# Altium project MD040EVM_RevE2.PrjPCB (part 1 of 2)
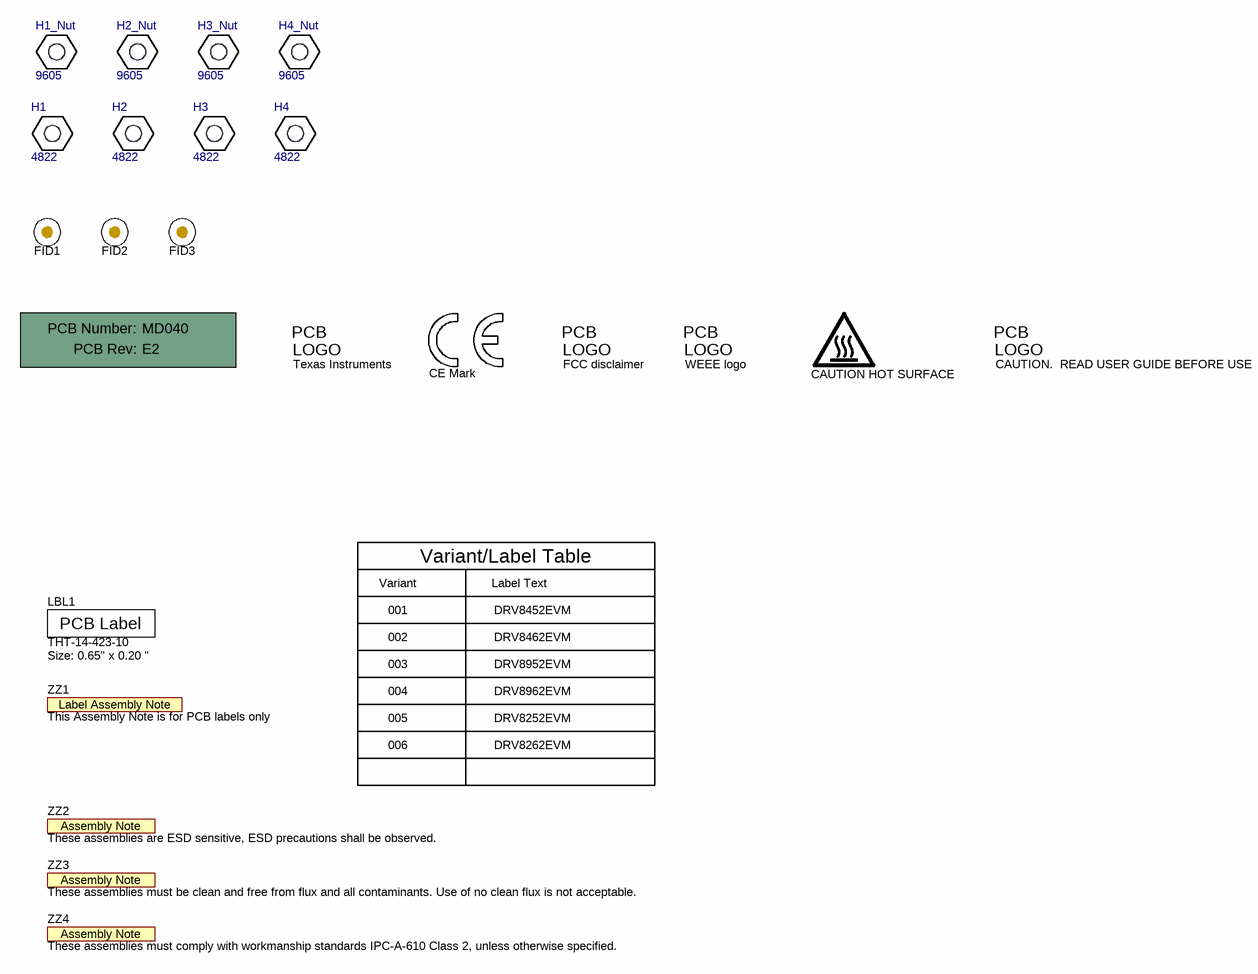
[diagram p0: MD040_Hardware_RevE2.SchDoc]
CopyrightYear: 2021; PCB_Layout: Wang Li; PCB_Rev: E2; PRJ_Customer: Public Release; PRJ_Engineer: Wang Li; PRJ_Number: MD040; PRJ_Title: DRV8452EVM; SCH_Rev: E2; TechSupport: http://www.ti.com/support; TID: N/A
4 sheets, 334 parts. Net scope: global (net labels, ports and power ports of the same name join across sheets).
Board file: MD040_RevE2.PcbDoc
Sheets:
  MD040_Hardware_RevE2.SchDoc
  MD040_Motor_control_RevE2.SchDoc
  MD040_Motor_Driver_RevE2.SchDoc
  MD040_ezFET_RevE2.SchDoc

## Sheet MD040_Hardware_RevE2.SchDoc
size 431 x 279 mm; Date: Not shown in title block; ApprovedBy: Not shown in title block; CheckedBy: Not shown in title block; Author: Not shown in title block; CompanyName: Not shown in title block; Engineer: Not shown in title block; Organization: Not shown in title block; Address1: Not shown in title block; Address2: Not shown in title block; Address3: Not shown in title block; Address4: Not shown in title block; DocumentNumber: 3; Revision: Use project parameter SCH_Rev; SheetNumber: 3; SheetTotal: 3; PageSetup: Record=PageOptions¦CenterHorizontal=True¦CenterVertical=True¦PrintScale=1.00¦XCorrection=1.00¦YCorrection=1.00¦PrintKind=0¦BorderSize=5000000¦LeftOffset=0¦BottomOffset=0¦Orientation=2¦PaperLength=1000¦PaperWidth=1000¦Scale=100¦PaperSource=15¦PrintQuality=600¦MediaType=1¦DitherType=10¦PaperKind=Letter¦PrintScaleMode=1

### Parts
!PCB1  Printed Circuit Board  (value not drawn)  (mechanical)
FID1  Fiducial  [Fiducial10-20]  (value not drawn)
FID2  Fiducial  [Fiducial10-20]  (value not drawn)
FID3  Fiducial  [Fiducial10-20]  (value not drawn)
H1  4822  [KEYSTONE_4822]
H1_Nut  9605  [Keystone_9605]
H2  4822  [KEYSTONE_4822]
H2_Nut  9605  [Keystone_9605]
H3  4822  [KEYSTONE_4822]
H3_Nut  9605  [Keystone_9605]
H4  4822  [KEYSTONE_4822]
H4_Nut  9605  [Keystone_9605]
LBL1  THT-14-423-10  Note: Size: 0.65" x 0.20 "  [Label_650x200]
LOGO1  CAUTION HOT SURFACE  [IEC_HotSurface_Small]  (no BOM)
Logo2  CE Mark  [CE_Mark_5mm]  (no BOM)
Logo3  Texas Instruments  [TI_Stacked_Overlay_Small]  (no BOM)
Logo4  FCC disclaimer  [FCC_disclaimer]  (no BOM)
Logo5  WEEE logo  [WEEE_Minimum]  (no BOM)
Logo6  CAUTION.  READ USER GUIDE BEFORE USE  [IEC_Caution_Small]  (no BOM)
ZZ1  This Assembly Note is for PCB labels only  [AssemblyNoteLabel]  (no BOM)
ZZ2  These assemblies are ESD sensitive, ESD precautions shall be observed.  [AssemblyNote]  (no BOM)
ZZ3  These assemblies must be clean and free from flux and all contaminants. Use of no clean flux is not acceptable.  [AssemblyNote]  (no BOM)
ZZ4  These assemblies must comply with workmanship standards IPC-A-610 Class 2, unless otherwise specified.  [AssemblyNote]  (no BOM)

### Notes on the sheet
- Variant
- Variant/Label Table
- Label Text
- 001
- 002
- DRV8452EVM
- DRV8462EVM
- 003
- 004
- 005
- DRV8952EVM
- DRV8962EVM
- DRV8252EVM
- 006
- DRV8262EVM

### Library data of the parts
!PCB1 = CMP-0003618-2: Manufacturer: Any; PartNumber: MD040
FID1-FID3 = CMP-0077181-1: Fiducial mark.  There is nothing to buy or mount.
H1-H4 = CMP-0003678-1: Standoff, Hex, 1.25"L #6-32 Nylon; Manufacturer: Keystone
H1_Nut H2_Nut H3_Nut H4_Nut = CMP-0003948-1: Small nylon hex nut, 0.10 thick with a 0.250 outside diameter and a 4-40 threading; Manufacturer: Keystone; CompType: Standoff
LBL1 = CMP-0003625-1: Thermal Transfer Printable Labels, 0.650" W x 0.200" H - 10,000 per roll; Manufacturer: Brady; CompType: Label
LOGO1 = CMP-0074837-1: IEC 61010-1 Hot Surface Warning; SymbolCreator: a0412235
Logo2 = CMP-0074844-1: SymbolCreator: a0412235
Logo3 = CMP-0074838-1: Texas Instrument Corporate Signature; SymbolCreator: a0412235; Lib Reference: TI_Logo; Library Reference: Logo
Logo4 = CMP-0074847-1: FCC_disclaimer; Library Reference: Logo
Logo5 = CMP-0074769-1
Logo6 = CMP-0074836-1: IEC 61010-1 Caution Warning; SymbolCreator: a0412235; Lib Reference: IEC_Caution
ZZ1 = CMP-0003616-3
ZZ2 = CMP-0077236-1
ZZ3 = CMP-0077237-1
ZZ4 = CMP-0077238-1

## Sheet MD040_Motor_control_RevE2.SchDoc
size 431 x 279 mm; Date: Not shown in title block; ApprovedBy: Not shown in title block; CheckedBy: Not shown in title block; Author: Not shown in title block; CompanyName: Not shown in title block; Engineer: Not shown in title block; Organization: Not shown in title block; Address1: Not shown in title block; Address2: Not shown in title block; Address3: Not shown in title block; Address4: Not shown in title block; DocumentNumber: 2; Revision: Use project parameter SCH_Rev; SheetNumber: 2; SheetTotal: 3; PageSetup: Record=PageOptions¦CenterHorizontal=True¦CenterVertical=True¦PrintScale=1.00¦XCorrection=1.00¦YCorrection=1.00¦PrintKind=0¦BorderSize=5000000¦LeftOffset=0¦BottomOffset=0¦Orientation=2¦PaperLength=1000¦PaperWidth=1000¦Scale=100¦PaperSource=15¦PrintQuality=600¦MediaType=1¦DitherType=10¦PaperKind=Letter¦PrintScaleMode=1
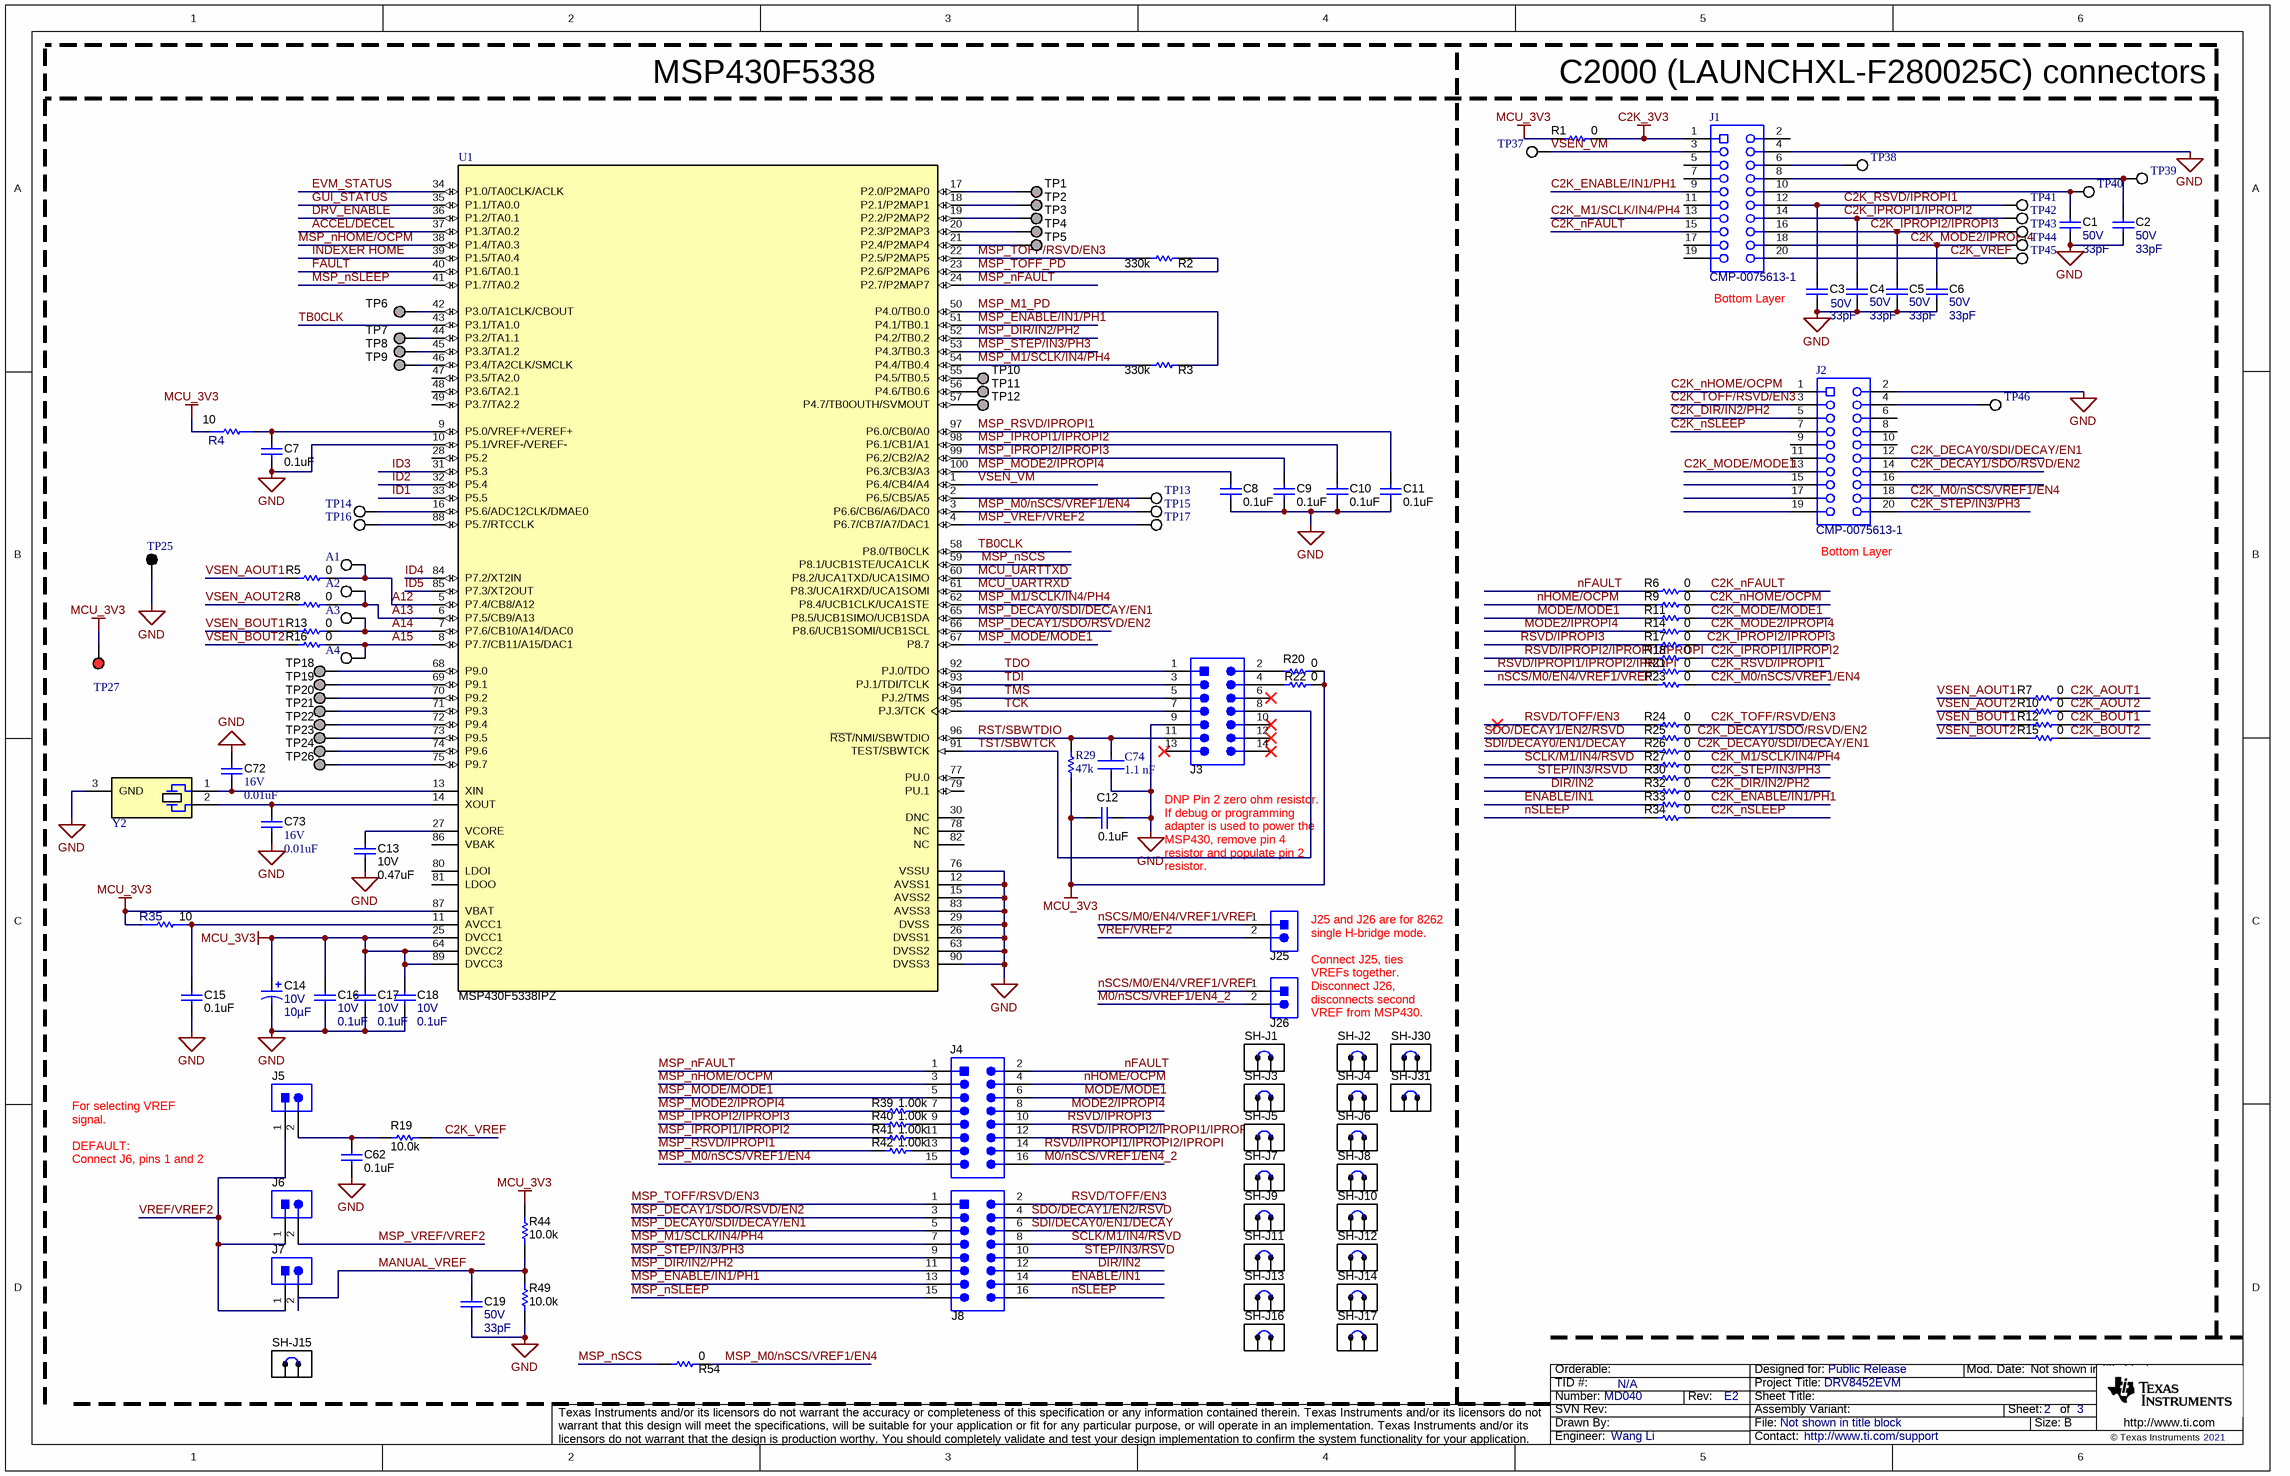
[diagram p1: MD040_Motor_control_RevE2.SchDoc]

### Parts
A1  5012  [Keystone5012]  (value not drawn)
A2  5012  [Keystone5012]  (value not drawn)
A3  5012  [Keystone5012]  (value not drawn)
A4  5012  [Keystone5012]  (value not drawn)
C1  VDC_V: 50V  ValueDisplayed: 33pF  [0402]  (hidden comment: C1005C0G1H330J050BA)
C2  VDC_V: 50V  ValueDisplayed: 33pF  [0402]  (hidden comment: C1005C0G1H330J050BA)
C3  VDC_V: 50V  ValueDisplayed: 33pF  [0402]  (hidden comment: C1005C0G1H330J050BA)
C4  VDC_V: 50V  ValueDisplayed: 33pF  [0402]  (hidden comment: C1005C0G1H330J050BA)
C5  VDC_V: 50V  ValueDisplayed: 33pF  [0402]  (hidden comment: C1005C0G1H330J050BA)
C6  VDC_V: 50V  ValueDisplayed: 33pF  [0402]  (hidden comment: C1005C0G1H330J050BA)
C7  ValueDisplayed: 0.1uF  [0402L]  (hidden comment: 885012105010)
C8  ValueDisplayed: 0.1uF  [0402L]  (hidden comment: 885012105010)
C9  ValueDisplayed: 0.1uF  [0402L]  (hidden comment: 885012105010)
C10  ValueDisplayed: 0.1uF  [0402L]  (hidden comment: 885012105010)
C11  ValueDisplayed: 0.1uF  [0402L]  (hidden comment: 885012105010)
C12  ValueDisplayed: 0.1uF  [0402L]  (hidden comment: 885012105010)
C13  VDC_V: 10V  ValueDisplayed: 0.47uF  [0402]  (hidden comment: GRM155R61A474KE15D)
C14  VDC_V: 10V  ValueDisplayed: 10µF  [3216-18]  (hidden comment: T520A106M010ATE080)
C15  ValueDisplayed: 0.1uF  [0402L]  (hidden comment: 885012105010)
C16  VDC_V: 10V  ValueDisplayed: 0.1uF  [0402]  (hidden comment: GRM155R61A104KA01D)
C17  VDC_V: 10V  ValueDisplayed: 0.1uF  [0402]  (hidden comment: GRM155R61A104KA01D)
C18  VDC_V: 10V  ValueDisplayed: 0.1uF  [0402]  (hidden comment: GRM155R61A104KA01D)
C19  VDC_V: 50V  ValueDisplayed: 33pF  [0402]  (hidden comment: C1005C0G1H330J050BA)
C62  ValueDisplayed: 0.1uF  [0402L]  (hidden comment: 885012105010)
C72  VDC_V: 16V  ValueDisplayed: 0.01uF  [0402]  (hidden comment: 885012205031)
C73  VDC_V: 16V  ValueDisplayed: 0.01uF  [0402]  (hidden comment: 885012205031)
C74  1.1 nF  [FP-C0805C-DN-MFG]
J1  CMP-0075613-1  [Samtec_SSQ-110-03-x-D]
J2  CMP-0075613-1  [Samtec_SSQ-110-03-x-D]
J3  Header_7x2_PEC07DAAN  [CONN_PEC07DAAN]  (value not drawn)
J4  TSM-108-01-L-DV  [Samtec_TSM-108-01-x-DV]  (value not drawn)
J5  PBC02SAAN  [Sullins_PBC02SAAN]  (value not drawn)
J6  PBC02SAAN  [Sullins_PBC02SAAN]  (value not drawn)
J7  PBC02SAAN  [Sullins_PBC02SAAN]  (value not drawn)
J8  TSM-108-01-L-DV  [Samtec_TSM-108-01-x-DV]  (value not drawn)
J25  PBC02SAAN  [Sullins_PBC02SAAN]  (value not drawn)
J26  PBC02SAAN  [Sullins_PBC02SAAN]  (value not drawn)
R1  value 0  [0402L]  (hidden comment: Resistor)
R2  ValueDisplayed: 330k  [0603L]  (hidden comment: CRCW0603330KJNEA)
R3  ValueDisplayed: 330k  [0603L]  (hidden comment: CRCW0603330KJNEA)
R4  Res_ohm: 10  [FP-CH0402-10RJFPT_0402-MFG]  (hidden comment: CH0402-10RJFPT)
R5  value 0  [0402L]  (hidden comment: Resistor)
R6  value 0  [0402L]  (hidden comment: Resistor)
R7  value 0  [0402L]  (hidden comment: Resistor)
R8  value 0  [0402L]  (hidden comment: Resistor)
R9  value 0  [0402L]  (hidden comment: Resistor)
R10  value 0  [0402L]  (hidden comment: Resistor)
R11  value 0  [0402L]  (hidden comment: Resistor)
R12  value 0  [0402L]  (hidden comment: Resistor)
R13  value 0  [0402L]  (hidden comment: Resistor)
R14  value 0  [0402L]  (hidden comment: Resistor)
R15  value 0  [0402L]  (hidden comment: Resistor)
R16  value 0  [0402L]  (hidden comment: Resistor)
R17  value 0  [0402L]  (hidden comment: Resistor)
R18  value 0  [0402L]  (hidden comment: Resistor)
R19  ValueDisplayed: 10.0k  [0603]  (hidden comment: CRCW060310K0FKEA)
R20  value 0  [0402L]  (hidden comment: Resistor)
R21  value 0  [0402L]  (hidden comment: Resistor)
R22  value 0  [0402L]  (hidden comment: Resistor)
R23  value 0  [0402L]  (hidden comment: Resistor)
R24  value 0  [0402L]  (hidden comment: Resistor)
R25  value 0  [0402L]  (hidden comment: Resistor)
R26  value 0  [0402L]  (hidden comment: Resistor)
R27  value 0  [0402L]  (hidden comment: Resistor)
R29  47k  [RESC1005X40X25ML05T10]
R30  value 0  [0402L]  (hidden comment: Resistor)
R32  value 0  [0402L]  (hidden comment: Resistor)
R33  value 0  [0402L]  (hidden comment: Resistor)
R34  value 0  [0402L]  (hidden comment: Resistor)
R35  Res_ohm: 10  [FP-CH0402-10RJFPT_0402-MFG]  (hidden comment: CH0402-10RJFPT)
R39  ValueDisplayed: 1.00k  [0402L]  (hidden comment: CRCW04021K00FKED)
R40  ValueDisplayed: 1.00k  [0402L]  (hidden comment: CRCW04021K00FKED)
R41  ValueDisplayed: 1.00k  [0402L]  (hidden comment: CRCW04021K00FKED)
R42  ValueDisplayed: 1.00k  [0402L]  (hidden comment: CRCW04021K00FKED)
R44  ValueDisplayed: 10.0k  [0603]  (hidden comment: CRCW060310K0FKEA)
R49  ValueDisplayed: 10.0k  [0603]  (hidden comment: CRCW060310K0FKEA)
R54  value 0  [0402L]  (hidden comment: Resistor)
SH-J1  SNT-100-BK-G  [SNT-100-BK-G]  (value not drawn)
SH-J2  SNT-100-BK-G  [SNT-100-BK-G]  (value not drawn)
SH-J3  SNT-100-BK-G  [SNT-100-BK-G]  (value not drawn)
SH-J4  SNT-100-BK-G  [SNT-100-BK-G]  (value not drawn)
SH-J5  SNT-100-BK-G  [SNT-100-BK-G]  (value not drawn)
SH-J6  SNT-100-BK-G  [SNT-100-BK-G]  (value not drawn)
SH-J7  SNT-100-BK-G  [SNT-100-BK-G]  (value not drawn)
SH-J8  SNT-100-BK-G  [SNT-100-BK-G]  (value not drawn)
SH-J9  SNT-100-BK-G  [SNT-100-BK-G]  (value not drawn)
SH-J10  SNT-100-BK-G  [SNT-100-BK-G]  (value not drawn)
SH-J11  SNT-100-BK-G  [SNT-100-BK-G]  (value not drawn)
SH-J12  SNT-100-BK-G  [SNT-100-BK-G]  (value not drawn)
SH-J13  SNT-100-BK-G  [SNT-100-BK-G]  (value not drawn)
SH-J14  SNT-100-BK-G  [SNT-100-BK-G]  (value not drawn)
SH-J15  SNT-100-BK-G  [SNT-100-BK-G]  (value not drawn)
SH-J16  SNT-100-BK-G  [SNT-100-BK-G]  (value not drawn)
SH-J17  SNT-100-BK-G  [SNT-100-BK-G]  (value not drawn)
SH-J30  SNT-100-BK-G  [SNT-100-BK-G]  (value not drawn)
SH-J31  SNT-100-BK-G  [SNT-100-BK-G]  (value not drawn)
TP1  TP_H0.45P0.75  [TP_H045P075]  (value not drawn)  (no BOM)
TP2  TP_H0.45P0.75  [TP_H045P075]  (value not drawn)  (no BOM)
TP3  TP_H0.45P0.75  [TP_H045P075]  (value not drawn)  (no BOM)
TP4  TP_H0.45P0.75  [TP_H045P075]  (value not drawn)  (no BOM)
TP5  TP_H0.45P0.75  [TP_H045P075]  (value not drawn)  (no BOM)
TP6  TP_H0.45P0.75  [TP_H045P075]  (value not drawn)  (no BOM)
TP7  TP_H0.45P0.75  [TP_H045P075]  (value not drawn)  (no BOM)
TP8  TP_H0.45P0.75  [TP_H045P075]  (value not drawn)  (no BOM)
TP9  TP_H0.45P0.75  [TP_H045P075]  (value not drawn)  (no BOM)
TP10  TP_H0.45P0.75  [TP_H045P075]  (value not drawn)  (no BOM)
TP11  TP_H0.45P0.75  [TP_H045P075]  (value not drawn)  (no BOM)
TP12  TP_H0.45P0.75  [TP_H045P075]  (value not drawn)  (no BOM)
TP13  5012  [Keystone5012]  (value not drawn)
TP14  5012  [Keystone5012]  (value not drawn)
TP15  5012  [Keystone5012]  (value not drawn)
TP16  5012  [Keystone5012]  (value not drawn)
TP17  5012  [Keystone5012]  (value not drawn)
TP18  TP_H0.45P0.75  [TP_H045P075]  (value not drawn)  (no BOM)
TP19  TP_H0.45P0.75  [TP_H045P075]  (value not drawn)  (no BOM)
TP20  TP_H0.45P0.75  [TP_H045P075]  (value not drawn)  (no BOM)
TP21  TP_H0.45P0.75  [TP_H045P075]  (value not drawn)  (no BOM)
TP22  TP_H0.45P0.75  [TP_H045P075]  (value not drawn)  (no BOM)
TP23  TP_H0.45P0.75  [TP_H045P075]  (value not drawn)  (no BOM)
TP24  TP_H0.45P0.75  [TP_H045P075]  (value not drawn)  (no BOM)
TP25  5011  [Keystone5011]  (value not drawn)
TP26  TP_H0.45P0.75  [TP_H045P075]  (value not drawn)  (no BOM)
TP27  5010  [Keystone5010]  (value not drawn)
TP37  5012  [Keystone5012]  (value not drawn)
TP38  5012  [Keystone5012]  (value not drawn)
TP39  5012  [Keystone5012]  (value not drawn)
TP40  5012  [Keystone5012]  (value not drawn)
TP41  5012  [Keystone5012]  (value not drawn)
TP42  5012  [Keystone5012]  (value not drawn)
TP43  5012  [Keystone5012]  (value not drawn)
TP44  5012  [Keystone5012]  (value not drawn)
TP45  5012  [Keystone5012]  (value not drawn)
TP46  5012  [Keystone5012]  (value not drawn)
U1  MSP430F5338IPZ  [PZT0100A_N]
Y2  MS3V-T1R 32.768KHZ +/-20PPM 12.5PF  [XTAL_MS3V-T1R]  (value not drawn)

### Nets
C2K_3V3: J1.1 R1.2
GND: C1.2 C2.2 C3.2 C4.2 C5.2 C6.2 C7.1 C8.1 C9.1 C10.1 C11.1 C12.2 C13.2 C14.2(-) C15.1 C16.2 C17.2 C18.2 C19.2 C62.1 C72.2 C73.1 C74.2 J1.4 J2.2 J3.9 R49.1 TP25.1 U1.10(P5.1/VREF-/VEREF-) U1.12(AVSS1) U1.15(AVSS2) U1.26(DVSS1) U1.29(DVSS) U1.63(DVSS2) U1.76(VSSU) U1.83(AVSS3) U1.90(DVSS3) Y2.3(GND)
MCU_3V3: C12.1 C14.1(+) C16.1 C17.1 C18.1 R1.1 R4.1 R20.2 R22.2 R29.1 R35.1 R44.2 TP27.1 U1.25(DVCC1) U1.64(DVCC2) U1.87(VBAT) U1.89(DVCC3)
A12: A1.1 R5.2 U1.5(P7.4/CB8/A12)
A13: A2.1 R8.2 U1.6(P7.5/CB9/A13)
A14: A3.1 R13.2 U1.7(P7.6/CB10/A14/DAC0)
A15: A4.1 R16.2 U1.8(P7.7/CB11/A15/DAC1)
ACCEL/DECEL: U1.37(P1.3/TA0.2)
C2K_AOUT1: R7.2
C2K_AOUT2: R10.2
C2K_BOUT1: R12.2
C2K_BOUT2: R15.2
C2K_DECAY0/SDI/DECAY/EN1: J2.12 R26.2
C2K_DECAY1/SDO/RSVD/EN2: J2.14 R25.2
C2K_DIR/IN2/PH2: J2.5 R32.2
C2K_ENABLE/IN1/PH1: J1.9 R33.2
C2K_IPROPI1/IPROPI2: C4.1 J1.14 R18.2 TP42.1
C2K_IPROPI2/IPROPI3: C5.1 J1.16 R17.2 TP43.1
C2K_M0/nSCS/VREF1/EN4: J2.18 R23.2
C2K_M1/SCLK/IN4/PH4: J1.13 R27.2
C2K_MODE2/IPROPI4: C6.1 J1.18 R14.2 TP44.1
C2K_MODE/MODE1: J2.13 R11.2
C2K_nFAULT: J1.15 R6.2
C2K_nHOME/OCPM: J2.1 R9.2
C2K_nSLEEP: J2.7 R34.2
C2K_RSVD/IPROPI1: C3.1 J1.12 R21.2 TP41.1
C2K_STEP/IN3/PH3: J2.20 R30.2
C2K_TOFF/RSVD/EN3: J2.3 R24.2
C2K_VREF: J1.20 R19.1 TP45.1
DIR/IN2: J8.12 R32.1
DRV_ENABLE: U1.36(P1.2/TA0.1)
ENABLE/IN1: J8.14 R33.1
EVM_STATUS: U1.34(P1.0/TA0CLK/ACLK)
FAULT: U1.40(P1.6/TA0.1)
GUI_STATUS: U1.35(P1.1/TA0.0)
ID1: U1.33(P5.5)
ID2: U1.32(P5.4)
ID3: U1.31(P5.3)
ID4: U1.84(P7.2/XT2IN)
ID5: U1.85(P7.3/XT2OUT)
INDEXER HOME: U1.39(P1.5/TA0.4)
M0/nSCS/VREF1/EN4_2: J4.16 J26.2
MANUAL_VREF: C19.1 J7.2 R44.1 R49.2
MCU_UARTRXD: U1.61(P8.3/UCA1RXD/UCA1SOMI)
MCU_UARTTXD: U1.60(P8.2/UCA1TXD/UCA1SIMO)
MODE2/IPROPI4: J4.8 R14.1
MODE/MODE1: J4.6 R11.1
MSP_DECAY0/SDI/DECAY/EN1: J8.5 U1.65(P8.5/UCB1SIMO/UCB1SDA)
MSP_DECAY1/SDO/RSVD/EN2: J8.3 U1.66(P8.6/UCB1SOMI/UCB1SCL)
MSP_DIR/IN2/PH2: J8.11 U1.52(P4.2/TB0.2)
MSP_ENABLE/IN1/PH1: J8.13 U1.51(P4.1/TB0.1)
MSP_IPROPI1/IPROPI2: C10.2 R41.1 U1.98(P6.1/CB1/A1)
MSP_IPROPI2/IPROPI3: C9.2 R40.1 U1.99(P6.2/CB2/A2)
MSP_M0/nSCS/VREF1/EN4: J4.15 R54.2 TP15.1 U1.3(P6.6/CB6/A6/DAC0)
MSP_M1/SCLK/IN4/PH4: J8.7 R3.1 U1.54(P4.4/TB0.4) U1.62(P8.4/UCB1CLK/UCA1STE)
MSP_M1_PD: R3.2 U1.50(P4.0/TB0.0)
MSP_MODE2/IPROPI4: C8.2 R39.1 U1.100(P6.3/CB3/A3)
MSP_MODE/MODE1: J4.5 U1.67(P8.7)
MSP_nFAULT: J4.1 U1.24(P2.7/P2MAP7)
MSP_nHOME/OCPM: J4.3 U1.38(P1.4/TA0.3)
MSP_nSCS: R54.1 U1.59(P8.1/UCB1STE/UCA1CLK)
MSP_nSLEEP: J8.15 U1.41(P1.7/TA0.2)
MSP_RSVD/IPROPI1: C11.2 R42.1 U1.97(P6.0/CB0/A0)
MSP_STEP/IN3/PH3: J8.9 U1.53(P4.3/TB0.3)
MSP_TOFF/RSVD/EN3: J8.1 R2.1 U1.22(P2.5/P2MAP5)
MSP_TOFF_PD: R2.2 U1.23(P2.6/P2MAP6)
MSP_VREF/VREF2: J6.2 TP17.1 U1.4(P6.7/CB7/A7/DAC1)
nFAULT: J4.2 R6.1
nHOME/OCPM: J4.4 R9.1
nSCS/M0/EN4/VREF1/VREF: J25.1 J26.1 R23.1
nSLEEP: J8.16 R34.1
RST/SBWTDIO: C74.1 J3.11 R29.2 U1.96(~{RST}/NMI/SBWTDIO)
RSVD/IPROPI1/IPROPI2/IPROPI: J4.14 R21.1
RSVD/IPROPI2/IPROPI1/IPROPI: J4.12 R18.1
RSVD/IPROPI3: J4.10 R17.1
RSVD/TOFF/EN3: J8.2 R24.1
SCLK/M1/IN4/RSVD: J8.8 R27.1
SDI/DECAY0/EN1/DECAY: J8.6 R26.1
SDO/DECAY1/EN2/RSVD: J8.4 R25.1
STEP/IN3/RSVD: J8.10 R30.1
TB0CLK: U1.43(P3.1/TA1.0) U1.58(P8.0/TB0CLK)
TCK: J3.7 U1.95(PJ.3/TCK)
TDI: J3.3 U1.93(PJ.1/TDI/TCLK)
TDO: J3.1 U1.92(PJ.0/TDO)
TMS: J3.5 U1.94(PJ.2/TMS)
TST/SBWTCK: J3.8 U1.91(TEST/SBWTCK)
VREF/VREF2: J5.1 J6.1 J7.1 J25.2
VSEN_AOUT1: R5.1 R7.1
VSEN_AOUT2: R8.1 R10.1
VSEN_BOUT1: R12.1 R13.1
VSEN_BOUT2: R15.1 R16.1
VSEN_VM: J1.3 TP37.1 U1.1(P6.4/CB4/A4)
NetC1_1: C1.1 J1.10 TP40.1
NetC2_1: C2.1 J1.8 TP39.1
NetC7_2: C7.2 R4.2 U1.9(P5.0/VREF+/VEREF+)
NetC13_1: C13.1 U1.27(VCORE)
NetC15_2: C15.2 R35.2 U1.11(AVCC1)
NetC62_2: C62.2 J5.2 R19.2
NetC72_1: C72.1 U1.13(XIN) Y2.1
NetC73_2: C73.2 U1.14(XOUT) Y2.2
NetJ1_6: J1.6 TP38.1
NetJ2_4: J2.4 TP46.1
NetJ3_2: J3.2 R20.1
NetJ3_4: J3.4 R22.1
NetJ4_7: J4.7 R39.2
NetJ4_9: J4.9 R40.2
NetJ4_11: J4.11 R41.2
NetJ4_13: J4.13 R42.2
NetTP1_1: TP1.1 U1.17(P2.0/P2MAP0)
NetTP2_1: TP2.1 U1.18(P2.1/P2MAP1)
NetTP3_1: TP3.1 U1.19(P2.2/P2MAP2)
NetTP4_1: TP4.1 U1.20(P2.3/P2MAP3)
NetTP5_1: TP5.1 U1.21(P2.4/P2MAP4)
NetTP6_1: TP6.1 U1.42(P3.0/TA1CLK/CBOUT)
NetTP7_1: TP7.1 U1.44(P3.2/TA1.1)
NetTP8_1: TP8.1 U1.45(P3.3/TA1.2)
NetTP9_1: TP9.1 U1.46(P3.4/TA2CLK/SMCLK)
NetTP10_1: TP10.1 U1.55(P4.5/TB0.5)
NetTP11_1: TP11.1 U1.56(P4.6/TB0.6)
NetTP12_1: TP12.1 U1.57(P4.7/TB0OUTH/SVMOUT)
NetTP13_1: TP13.1 U1.2(P6.5/CB5/A5)
NetTP14_1: TP14.1 U1.16(P5.6/ADC12CLK/DMAE0)
NetTP16_1: TP16.1 U1.88(P5.7/RTCCLK)
NetTP18_1: TP18.1 U1.68(P9.0)
NetTP19_1: TP19.1 U1.69(P9.1)
NetTP20_1: TP20.1 U1.70(P9.2)
NetTP21_1: TP21.1 U1.71(P9.3)
NetTP22_1: TP22.1 U1.72(P9.4)
NetTP23_1: TP23.1 U1.73(P9.5)
NetTP24_1: TP24.1 U1.74(P9.6)
NetTP26_1: TP26.1 U1.75(P9.7)

Not connected (* = marked no-connect by the designer): J1 2 5 7 11 17 19; J2 6 8 9 10 11 15 16 17 19; J3 6* 10* 12* 13* 14*; U1 28(P5.2) 30(DNC) 47(P3.5/TA2.0) 48(P3.6/TA2.1) 49(P3.7/TA2.2) 77(PU.0) 78(NC) 79(PU.1) 80(LDOI) 81(LDOO) 82(NC) 86(VBAK)

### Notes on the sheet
- MSP430F5338
- C2000 (LAUNCHXL-F280025C) connectors
- Bottom Layer
- (near J2) Bottom Layer
- DNP Pin 2 zero ohm resistor. If debug or programming adapter is used to power the MSP430, remove pin 4 resistor and populate pin 2 resistor.
- J25 and J26 are for 8262 single H-bridge mode.
  Connect J25, ties VREFs together. Disconnect J26, disconnects second VREF from MSP430.
- For selecting VREF signal.
  DEFAULT:
  Connect J6, pins 1 and 2

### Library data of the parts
A1-A4 TP13-TP17 TP37-TP46 = CMP-0055149-1: Test Point, Multipurpose, White, TH; Manufacturer: Keystone; CNHeader: FALSE; Green_Lifecycle: Active; Green_REACh: Passed; ContactFinish: Silver; CT: TRUE
C1-C6 C19 = CMP-0006250-2: CAP, CERM, 33 pF, 50 V, +/- 5%, C0G/NP0, 0402; Manufacturer: TDK; TaMin_C: -55°C; Polarized: N; SizeAreaWB_mm2: 3; Value1: Unknown; U/M: EA; Value: 33pF; TaMax_C: 125°C; SizeZ_mm: 0.6; SizeX_mm: 1; SizeY_mm: 0.5; AEC Category: Q200
C7-C12 C15 C62 = CMP-0006221-1: CAP, CERM, 0.1 uF, 10 V, +/- 20%, X5R, 0402; Manufacturer: Wurth Elektronik; Value: 0.1uF; Polarized: N; U/M: EA; Cap_F: 100nF; Value1: Unknown; VDC_V: 10V; TaMin_C: -55°C; TaMax_C: 85°C; Cap_Case: 0402; AEC Category: Q200; SizeArea_mm2: 0.5; SizeAreaWB_mm2: 3; SizeX_mm: 1; SizeZ_mm: 0.6
C13 = CMP-0006580-1: CAP, CERM, 0.47 uF, 10 V, +/- 10%, X5R, 0402; Manufacturer: MuRata; TaMin_C: -55°C; Polarized: N; SizeAreaWB_mm2: 3; Value1: Unknown; U/M: EA; Value: 0.47uF; TaMax_C: 85°C; SizeZ_mm: 0.6; SizeX_mm: 1; SizeY_mm: 0.5; Cap_F: 470nF; AEC Category: Q200
C14 = CMP-0084376-1: CAP, Tantalum Polymer, 10 µF, 10 V,+/- 20%, 0.08 ohm, 3216-18 SMD; Manufacturer: Kemet; TaMin_C: -55°C; SizeArea_mm2: 5.12; Value: 10uF; SizeAreaWB_mm2: 10.92; SizeY_mm: 1.6; Polarized: Y; SizeX_mm: 3.2; AEC Qualified: N; TaMax_C: 105°C; SizeZ_mm: 1.8; ESR_ohm: 0.08; CompType: Capacitor; AEC Category: Q200
C16-C18 = CMP-0006562-2: CAP, CERM, 0.1 uF, 10 V, +/- 10%, X5R, 0402; Manufacturer: MuRata; TaMin_C: -55°C; Polarized: N; SizeAreaWB_mm2: 3; Value1: Unknown; U/M: EA; Value: 0.1uF; TaMax_C: 85°C; SizeZ_mm: 0.6; SizeX_mm: 1; SizeY_mm: 0.5; Cap_F: 100nF; AEC Category: Q200
C72 C73 = CMP-0006227-2: CAP, CERM, 0.01 uF, 16 V, +/- 10%, X7R, 0402; Manufacturer: Wurth Elektronik; TaMin_C: -55°C; Polarized: N; SizeAreaWB_mm2: 3; Value1: Unknown; U/M: EA; Value: 0.01uF; TaMax_C: 125°C; SizeZ_mm: 0.6; SizeX_mm: 1; SizeY_mm: 0.5; Cap_F: 10nF; AEC Category: Q200
C74 = CMP-1036-03017-2: CAP CER 1100PF 50V NP0 0805; Manufacturer: KEMET; Manufacturer Part Number: C0805C112F5GACTU; Value: 1,100 pF; Tolerance: 0.01; Material: Ceramic; Temperature Characteristic: C0G; Temperature Coefficient: 30ppm/°C
J1 J2 = CMP-0075613-1: Receptacle, 2.54mm, 10x2, Gold, TH; PartNumber: SSQ-110-03-G-D; Manufacturer: Samtec; CompType: Socket Strip; Pitch_mm: 2.54; Gender: Female; Row_Count: 2; Current_A: 6.3A; Voltage_V: 550V; Cert_CSA: Y; Cert_CULUS: N; CT: True; CNHeader: False
J3 = CMP-0002339-2: Header, 100mil, 7x2, Tin, TH; Manufacturer: Sullins Connector Solutions; Cert_UL: Y; Current_A: 3A; Gender: Male; Green_Lifecycle: Active; Green_REACh: Passed; Pitch_mm: 2.54; Row_Count: 2; Shrouded: N; Voltage_V: 1.8kV
J4 J8 = CMP-0075595-1: Header, 2.54mm, 8x2, Gold, SMT; Manufacturer: Samtec; Pitch_mm: 2.54; Gender: Male; Cert_CSA: Y; Current_A: 4.9A; Voltage_V: 475V; CT: False; Shrouded: N; Row_Count: 2; CNHeader: True
J5-J7 J25 J26 = CMP-0054566-1: Header, 100mil, 2x1, Gold, TH; Manufacturer: Sullins Connector Solutions; CNHeader: TRUE; Current_A: 3A; Green_Lifecycle: Active; Shrouded: N; Gender: Male; Green_REACh: Passed; Voltage_V: 1.8kV; Row_Count: 1; Pitch_mm: 2.54; CT: FALSE; Cert_UL: Y
R1 R5-R18 R20-R27 R30 R32-R34 R54 = CMP-0026992-3: RES, 0, 5%, 0.1 W, AEC-Q200 Grade 0, 0402; Manufacturer: Panasonic; PartNumber: ERJ-2GE0R00X; Value_Code: 0000; Power_W: 100mW; Value2: 0.1W; VDC_V: 50V; TempCo: 600 ppm/C; EIA_Code: E24; AEC Category: Q200; AEC Qualified: Y; SizeArea_mm2: 0.5; SizeAreaWB_mm2: 3; SizeX_mm: 1; SizeZ_mm: 0.6
R2 R3 = CMP-0025784-3: RES, 330 k, 5%, 0.1 W, 0603; Manufacturer: Vishay-Dale; Power_W: 100mW; TempCo: 200 ppm/C; U/M: EA; Value: 330k; EIA_Code: E24; SizeX_mm: 1.6; SizeY_mm: 0.8; SizeZ_mm: 1; Value2: 0.1W; SizeArea_mm2: 1.28; VDC_V: 75V; AEC Category: Q200
R4 R35 = CMP-0091848-1: 10 Ohms ±5% 0.05W, 1/20W Chip Resistor 0402 (1005 Metric) RF, High Frequency Thin Film; Manufacturer: Vishay; SizeZ_mm: 0.627mm; VDC_V: 37V; TempCo: 100ppm/°C; Power_W: 50mW; AEC Qualified: No; Value: 10
R19 R44 R49 = CMP-0021998-3: RES, 10.0 k, 1%, 0.1 W, 0603; Manufacturer: Vishay-Dale; Power_W: 100mW; TempCo: 100 ppm/C; Value_Code: 10k0; U/M: EA; Value: 10.0k; EIA_Code: E96; Res_ohm: 10k; SizeX_mm: 1.6; SizeY_mm: 0.8; SizeZ_mm: 1; Value2: 0.1W; SizeArea_mm2: 1.28; VDC_V: 75V; AEC Category: Q200
R29 = CMP-2002-07701-1: Part Number: RC0402FR-0747KL; Manufacturer: Yageo / Phycomp
R39-R42 = CMP-0026071-2: RES, 1.00 k, 1%, 0.063 W, 0402; Manufacturer: Vishay-Dale; Power_W: 63mW; TempCo: 100 ppm/C; Value_Code: 1k00; U/M: EA; Value: 1.00k; EIA_Code: E96; Res_ohm: 1k; SizeX_mm: 1; SizeY_mm: 0.5; SizeZ_mm: 0.6; Value2: 0.063W; VDC_V: 50V; AEC Category: Q200
SH-J1-SH-J17 SH-J30 SH-J31 = CMP-0003623-1: Shunt, 100mil, Gold plated, Black; Alternate PartNumber: 969102-0000-DA; Manufacturer: Samtec; Alternate Manufacturer: 3M; Value: 1x2
TP1-TP12 TP18-TP24 TP26 = CMP-0003719-1: Testpoint; Manufacturer: Texas Instruments; CompType: Pad
TP25 = CMP-0055148-1: Test Point, Multipurpose, Black, TH; Manufacturer: Keystone; CNHeader: FALSE; Green_Lifecycle: Active; Green_REACh: Passed; ContactFinish: Silver; CT: TRUE
TP27 = CMP-0055147-1: Test Point, Multipurpose, Red, TH; Manufacturer: Keystone; CNHeader: FALSE; Green_Lifecycle: Active; Green_REACh: Passed; ContactFinish: Silver; CT: TRUE
U1 = CMP-0038879-1: 20 MHz Mixed Signal Microcontroller with 256 KB Flash, 18432 B SRAM and 74 GPIOs, -40 to 85 degC, 100-pin QFP (PZ), Green (RoHS & no Sb/Br); Manufacturer: Texas Instruments; Flash(KB): 256; USCI_B (I2C & SPI): 2; ADC Channels: 16; Comparators: Yes; Frequency(MHz): 20; DMA: 3; SRAM(B): 18432; Multiplier: 32x32; GPIO: 74; Timers - 16-bit: 4; SubFamily: 5 Series; ADC: 12-bit SAR
Y2 = CMP-0004566-4: Crystal, 32.768 kHz, 12.5pF, SMD; Manufacturer: Micro Crystal AG; TaMin_C: -40°C; TaMax_C: 85°C; AEC Category: Q200; AEC Qualified: N; Frequency Tolerance: 20 ppm

## Sheet MD040_Motor_Driver_RevE2.SchDoc
size 431 x 279 mm; Date: Not shown in title block; ApprovedBy: Not shown in title block; CheckedBy: Not shown in title block; Author: Not shown in title block; CompanyName: Not shown in title block; Engineer: Not shown in title block; Organization: Not shown in title block; Address1: Not shown in title block; Address2: Not shown in title block; Address3: Not shown in title block; Address4: Not shown in title block; DocumentNumber: 2; Revision: Use project parameter SCH_Rev; SheetNumber: 2; SheetTotal: 3; PageSetup: Record=PageOptions¦CenterHorizontal=True¦CenterVertical=True¦PrintScale=1.00¦XCorrection=1.00¦YCorrection=1.00¦PrintKind=0¦BorderSize=5000000¦LeftOffset=0¦BottomOffset=0¦Orientation=2¦PaperLength=1000¦PaperWidth=1000¦Scale=100¦PaperSource=15¦PrintQuality=600¦MediaType=1¦DitherType=10¦PaperKind=Letter¦PrintScaleMode=1
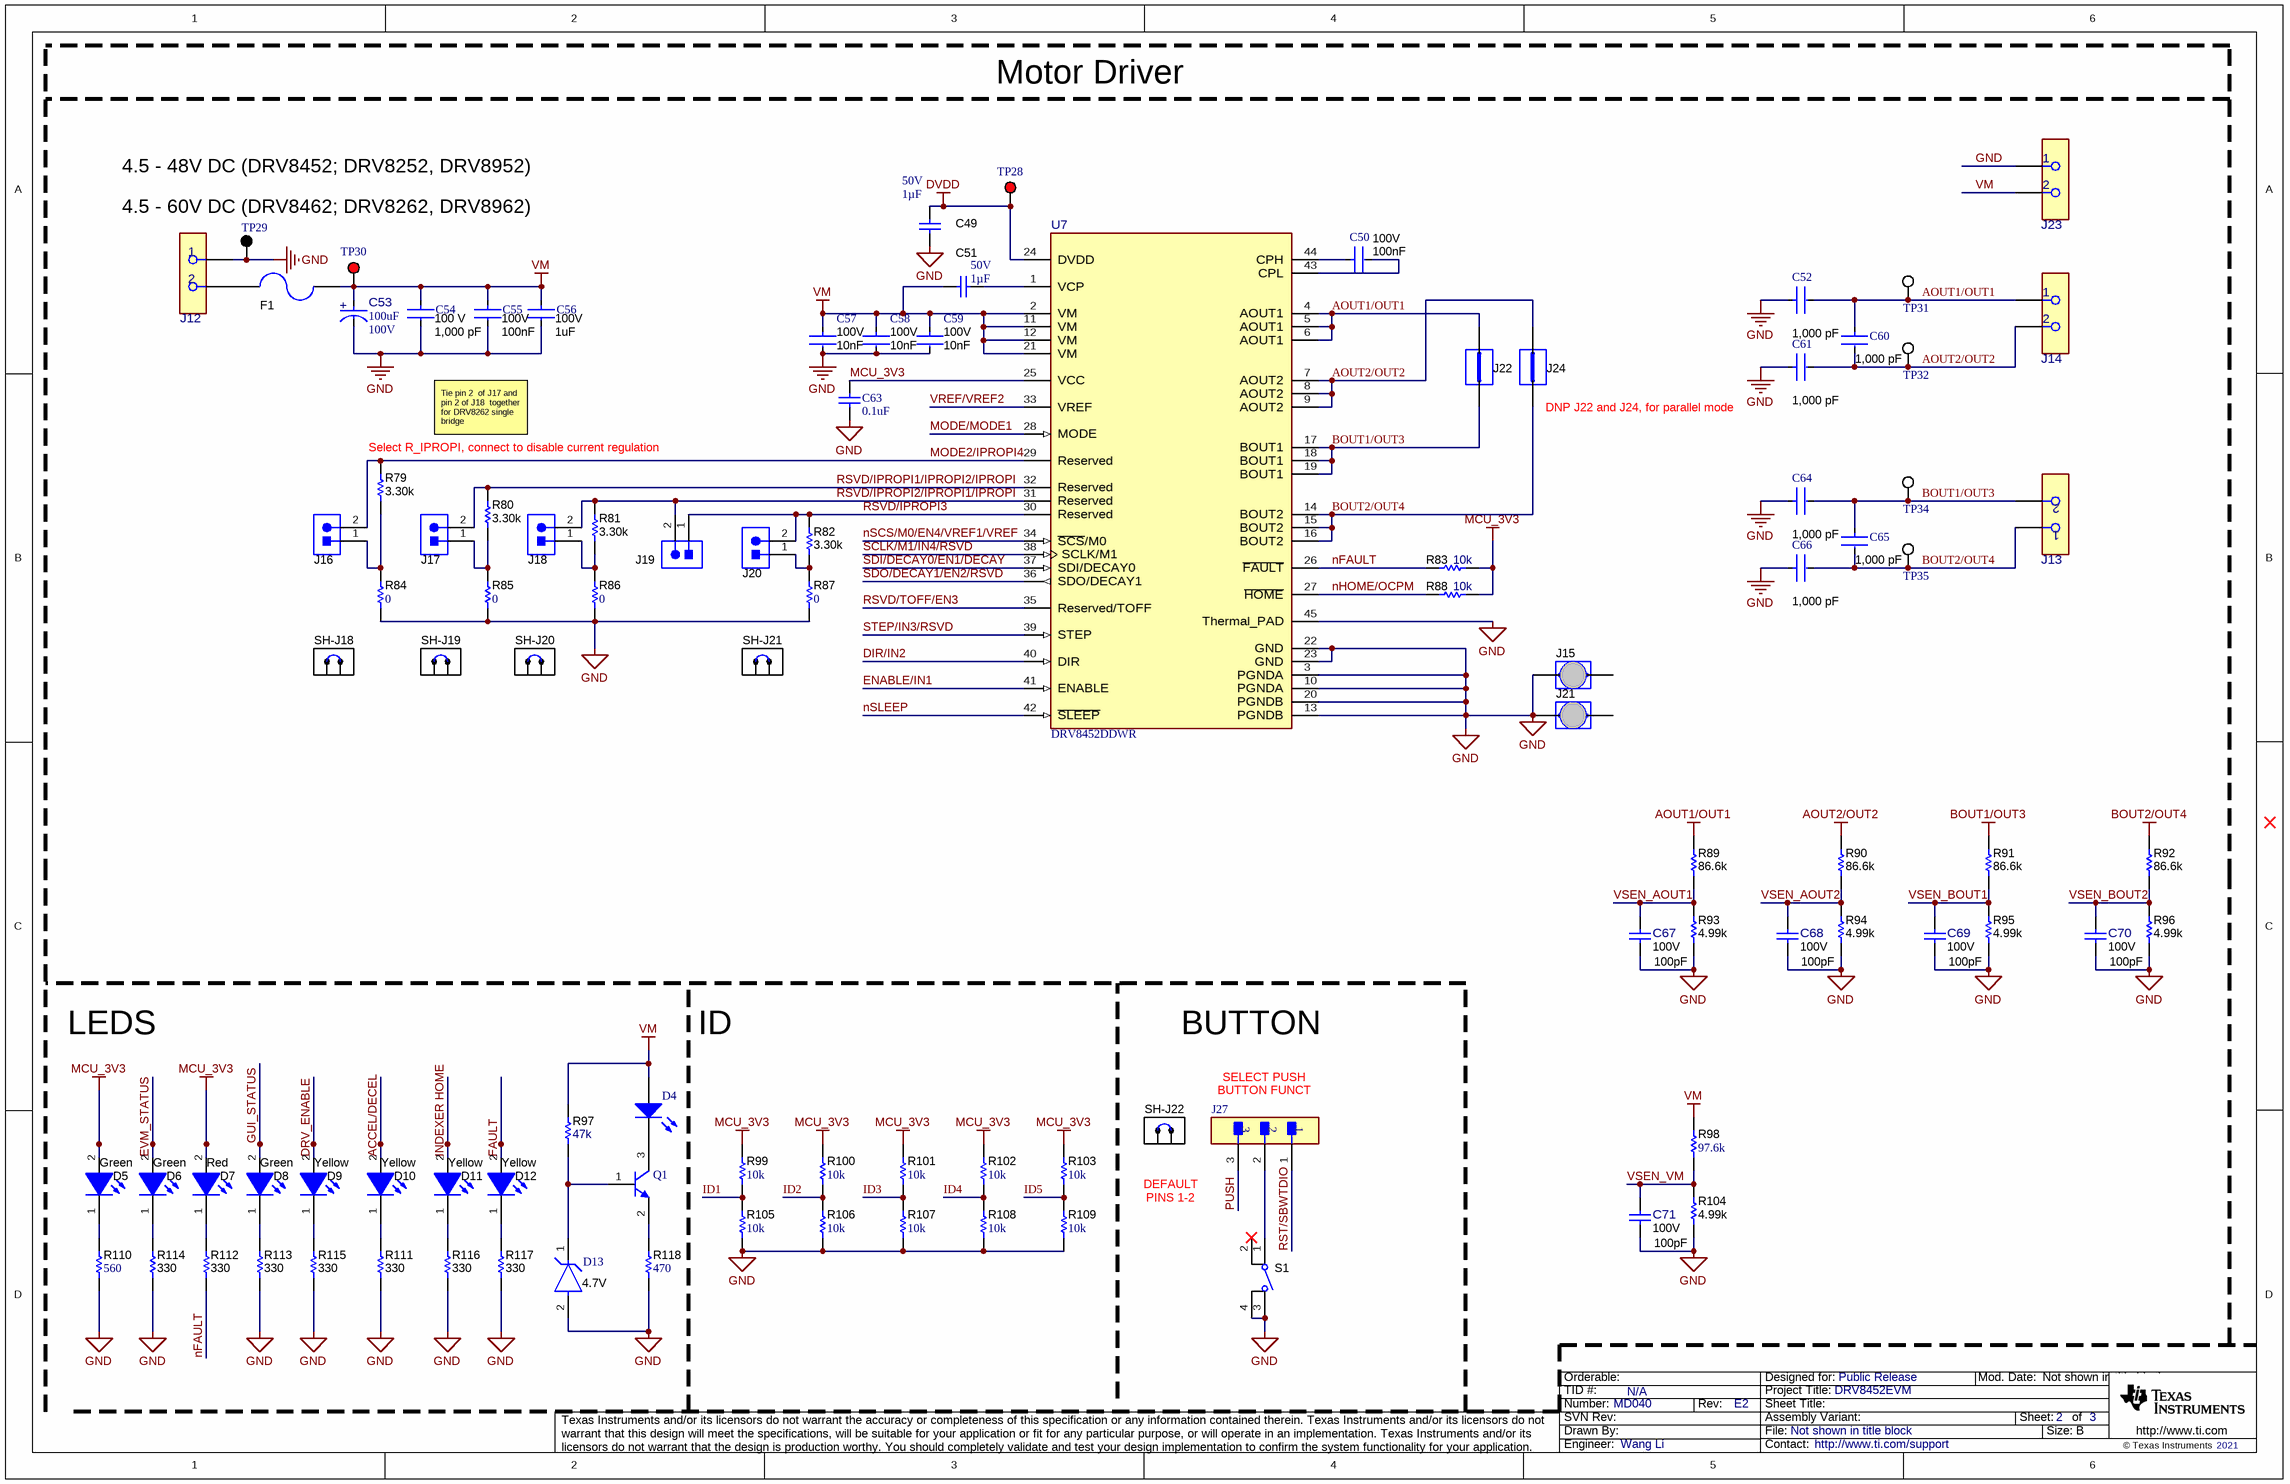
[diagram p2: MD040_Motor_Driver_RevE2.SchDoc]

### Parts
C49  Cap_F: 1µF  VDC_V: 50V  [0805_HV]  (hidden comment: C2012X7R1H105K125AB)
C50  Voltage Rating: 100V  Capacitance: 100nF  [FP-0603-L_1_6_0_1-W_0_8_0-IPC_B]  (hidden comment: HMK107BJ104MA-T)
C51  Cap_F: 1µF  VDC_V: 50V  [0805_HV]  (hidden comment: C2012X7R1H105K125AB)
C52  value 1,000 pF  [FP-C0603C-CF-MFG]  (hidden comment: C0603C102K1RACAUTO)
C53  ValueDisplayed: 100uF  VDC_V: 100V  [FP-EMVY101ARA101MKE0S_RADIAL-MFG]  (hidden comment: EMVY101ARA101MKE0S)
C54  value 1,000 pF  Voltage Rating: 100 V  [FP-C0603C-CF-MFG]  (hidden comment: C0603C102K1RACAUTO)
C55  Voltage Rating: 100V  Capacitance: 100nF  [FP-0603-L_1_6_0_1-W_0_8_0-IPC_B]  (hidden comment: HMK107BJ104MA-T)
C56  value 1uF  Voltage Rating: 100V  [FP-GRM21-0_2-MFG]  (hidden comment: GRM21BC72A105KE01L)
C57  Voltage Rating: 100V  Capacitance: 10nF  [FP-0603-L_1_6_0_1-W_0_8_0-IPC_A]  (hidden comment: HMK107B7103MA-T)
C58  Voltage Rating: 100V  Capacitance: 10nF  [FP-0603-L_1_6_0_1-W_0_8_0-IPC_A]  (hidden comment: HMK107B7103MA-T)
C59  Voltage Rating: 100V  Capacitance: 10nF  [FP-0603-L_1_6_0_1-W_0_8_0-IPC_A]  (hidden comment: HMK107B7103MA-T)
C60  value 1,000 pF  [FP-C0603C-CF-MFG]  (hidden comment: C0603C102K1RACAUTO)
C61  value 1,000 pF  [FP-C0603C-CF-MFG]  (hidden comment: C0603C102K1RACAUTO)
C63  0.1uF  [CAPC0603(1608)100_L]
C64  value 1,000 pF  [FP-C0603C-CF-MFG]  (hidden comment: C0603C102K1RACAUTO)
C65  value 1,000 pF  [FP-C0603C-CF-MFG]  (hidden comment: C0603C102K1RACAUTO)
C66  value 1,000 pF  [FP-C0603C-CF-MFG]  (hidden comment: C0603C102K1RACAUTO)
C67  VDC_V: 100V  Cap_F: 100pF  [FP-C0402C101J1HAC_0402-IPC_B]  (hidden comment: C0402C101J1HACTU)
C68  VDC_V: 100V  Cap_F: 100pF  [FP-C0402C101J1HAC_0402-IPC_B]  (hidden comment: C0402C101J1HACTU)
C69  VDC_V: 100V  Cap_F: 100pF  [FP-C0402C101J1HAC_0402-IPC_B]  (hidden comment: C0402C101J1HACTU)
C70  VDC_V: 100V  Cap_F: 100pF  [FP-C0402C101J1HAC_0402-IPC_B]  (hidden comment: C0402C101J1HACTU)
C71  VDC_V: 100V  Cap_F: 100pF  [FP-C0402C101J1HAC_0402-IPC_B]  (hidden comment: C0402C101J1HACTU)
D4  150060SS75000  [0603_A]  (value not drawn)
D5  value Green  [WL-SMCW_GREEN]  (hidden comment: 150060VS75000)
D6  value Green  [WL-SMCW_GREEN]  (hidden comment: 150060VS75000)
D7  value Red  [WL-SMCW_RED]  (hidden comment: 150060SS75000)
D8  value Green  [WL-SMCW_GREEN]  (hidden comment: 150060VS75000)
D9  value Yellow  [WL-SMCW_YELLOW]  (hidden comment: 150060YS75000)
D10  value Yellow  [WL-SMCW_YELLOW]  (hidden comment: 150060YS75000)
D11  value Yellow  [WL-SMCW_YELLOW]  (hidden comment: 150060YS75000)
D12  value Yellow  [WL-SMCW_YELLOW]  (hidden comment: 150060YS75000)
D13  Nom Zener Voltage: 4.7V  [FP-SOD323F-MFG]  (hidden comment: BZX84J-B4V7,115)
F1  0463015.ER  [Fuse_0463]  (value not drawn)
J12  691256610002  [FP-691256610002_HDR2-MFG]  (value not drawn)
J13  691250610002  [FP-691250610002_CONN_TERM_BLOCK2-MFG]  (value not drawn)
J14  691250610002  [FP-691250610002_CONN_TERM_BLOCK2-MFG]  (value not drawn)
J15  D3082-05  [Harwin_D3082-05]  (value not drawn)
J16  PBC02SAAN  [Sullins_PBC02SAAN]  (value not drawn)
J17  PBC02SAAN  [Sullins_PBC02SAAN]  (value not drawn)
J18  PBC02SAAN  [Sullins_PBC02SAAN]  (value not drawn)
J19  PBC02SAAN  [Sullins_PBC02SAAN]  (value not drawn)
J20  PBC02SAAN  [Sullins_PBC02SAAN]  (value not drawn)
J21  D3082-05  [Harwin_D3082-05]  (value not drawn)
J22  D3082-05  [Harwin_D3082-05]  (value not drawn)
J23  691250610002  [FP-691250610002_CONN_TERM_BLOCK2-MFG]  (value not drawn)
J24  D3082-05  [Harwin_D3082-05]  (value not drawn)
J27  PR20203VBNN  [FP-PR20203VBNN-MFG]  (value not drawn)
Q1  BC846BLT1G  [ONSC-SOT-23-3-318-08_V]  (value not drawn)
R79  ValueDisplayed: 3.30k  [0402L]  (hidden comment: ERJ-2RKF3301X)
R80  ValueDisplayed: 3.30k  [0402L]  (hidden comment: ERJ-2RKF3301X)
R81  ValueDisplayed: 3.30k  [0402L]  (hidden comment: ERJ-2RKF3301X)
R82  ValueDisplayed: 3.30k  [0402L]  (hidden comment: ERJ-2RKF3301X)
R83  ValueDisplayed: 10k  [0603L]  (hidden comment: RC0603JR-0710KL)
R84  ValueDisplayed: 0  [0402]  (hidden comment: CRCW04020000Z0EDHP)
R85  ValueDisplayed: 0  [0402]  (hidden comment: CRCW04020000Z0EDHP)
R86  ValueDisplayed: 0  [0402]  (hidden comment: CRCW04020000Z0EDHP)
R87  ValueDisplayed: 0  [0402]  (hidden comment: CRCW04020000Z0EDHP)
R88  ValueDisplayed: 10k  [0603L]  (hidden comment: RC0603JR-0710KL)
R89  ValueDisplayed: 86.6k  [0603L]  (hidden comment: CRCW060386K6FKEA)
R90  ValueDisplayed: 86.6k  [0603L]  (hidden comment: CRCW060386K6FKEA)
R91  ValueDisplayed: 86.6k  [0603L]  (hidden comment: CRCW060386K6FKEA)
R92  ValueDisplayed: 86.6k  [0603L]  (hidden comment: CRCW060386K6FKEA)
R93  ValueDisplayed: 4.99k  [0603L]  (hidden comment: CRCW06034K99FKEA)
R94  ValueDisplayed: 4.99k  [0603L]  (hidden comment: CRCW06034K99FKEA)
R95  ValueDisplayed: 4.99k  [0603L]  (hidden comment: CRCW06034K99FKEA)
R96  ValueDisplayed: 4.99k  [0603L]  (hidden comment: CRCW06034K99FKEA)
R97  ValueDisplayed: 47k  [0402]  (hidden comment: CRCW040247K0JNED)
R98  ValueDisplayed: 97.6k  [0603]  (hidden comment: RT0603DRE0797K6L)
R99  ValueDisplayed: 10k  [0603L]  (hidden comment: RC0603JR-0710KL)
R100  ValueDisplayed: 10k  [0603L]  (hidden comment: RC0603JR-0710KL)
R101  ValueDisplayed: 10k  [0603L]  (hidden comment: RC0603JR-0710KL)
R102  ValueDisplayed: 10k  [0603L]  (hidden comment: RC0603JR-0710KL)
R103  ValueDisplayed: 10k  [0603L]  (hidden comment: RC0603JR-0710KL)
R104  ValueDisplayed: 4.99k  [0603L]  (hidden comment: CRCW06034K99FKEA)
R105  ValueDisplayed: 10k  [0603L]  (hidden comment: RC0603JR-0710KL)
R106  ValueDisplayed: 10k  [0603L]  (hidden comment: RC0603JR-0710KL)
R107  ValueDisplayed: 10k  [0603L]  (hidden comment: RC0603JR-0710KL)
R108  ValueDisplayed: 10k  [0603L]  (hidden comment: RC0603JR-0710KL)
R109  ValueDisplayed: 10k  [0603L]  (hidden comment: RC0603JR-0710KL)
R110  ValueDisplayed: 560  [0603]  (hidden comment: RC0603FR-07560RL)
R111  ValueDisplayed: 330  [0603L]  (hidden comment: CMP-0025785-4)
R112  ValueDisplayed: 330  [0603L]  (hidden comment: CMP-0025785-4)
R113  ValueDisplayed: 330  [0603L]  (hidden comment: CMP-0025785-4)
R114  ValueDisplayed: 330  [0603L]  (hidden comment: CMP-0025785-4)
R115  ValueDisplayed: 330  [0603L]  (hidden comment: CMP-0025785-4)
R116  ValueDisplayed: 330  [0603L]  (hidden comment: CMP-0025785-4)
R117  ValueDisplayed: 330  [0603L]  (hidden comment: CMP-0025785-4)
R118  ValueDisplayed: 470  [0603]  (hidden comment: RC0603FR-07470RL)
S1  FSM4JSMA  [SW_FSM4JSMA]  (value not drawn)
SH-J18  SNT-100-BK-G  [SNT-100-BK-G]  (value not drawn)
SH-J19  SNT-100-BK-G  [SNT-100-BK-G]  (value not drawn)
SH-J20  SNT-100-BK-G  [SNT-100-BK-G]  (value not drawn)
SH-J21  SNT-100-BK-G  [SNT-100-BK-G]  (value not drawn)
SH-J22  SNT-100-BK-G  [SNT-100-BK-G]  (value not drawn)
TP28  5010  [Keystone5010]  (value not drawn)
TP29  5011  [Keystone5011]  (value not drawn)
TP30  5010  [Keystone5010]  (value not drawn)
TP31  5015  [Testpoint_Keystone_Miniature]  (value not drawn)
TP32  5015  [Testpoint_Keystone_Miniature]  (value not drawn)
TP34  5015  [Testpoint_Keystone_Miniature]  (value not drawn)
TP35  5015  [Testpoint_Keystone_Miniature]  (value not drawn)
U7  DRV8452DDWR  [DDW0044E-MFG]

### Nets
AOUT1/OUT1: C52.2 C60.1 J14.1 J22.2 R89.2 TP31.1 U7.4(AOUT1) U7.5(AOUT1) U7.6(AOUT1)
AOUT2/OUT2: C60.2 C61.2 J14.2 J24.2 R90.2 TP32.1 U7.7(AOUT2) U7.8(AOUT2) U7.9(AOUT2)
BOUT1/OUT3: C64.2 C65.1 J13.2 J22.1 R91.2 TP34.1 U7.17(BOUT1) U7.18(BOUT1) U7.19(BOUT1)
BOUT2/OUT4: C65.2 C66.2 J13.1 J24.1 R92.2 TP35.1 U7.14(BOUT2) U7.15(BOUT2) U7.16(BOUT2)
DVDD: C49.1 TP28.1 U7.24(DVDD)
GND: C49.2 C52.1 C53.1(CATHODE) C54.2 C55.2 C56.2 C57.2 C58.2 C59.2 C61.1 C63.1 C64.1 C66.1 C67.2 C68.2 C69.2 C70.2 C71.2 D13.2(A) J12.1 J15.1 J21.1 J23.1 R84.1 R85.1 R86.1 R87.1 R93.1 R94.1 R95.1 R96.1 R104.1 R105.2 R106.2 R107.2 R108.2 R109.2 R110.1 R111.1 R113.1 R114.1 R115.1 R116.1 R117.1 R118.1 S1.3 S1.4 TP29.1 U7.3(PGNDA) U7.10(PGNDA) U7.13(PGNDB) U7.20(PGNDB) U7.22(GND) U7.23(GND) U7.45(Thermal_PAD)
MCU_3V3: C63.2 D5.2(A) D7.2(A) R83.2 R88.2 R99.1 R100.1 R101.1 R102.1 R103.1 U7.25(VCC)
VM: C51.1 C53.2(ANODE) C54.1 C55.1 C56.1 C57.1 C58.1 C59.1 D4.2(A) F1.1 J23.2 R97.2 R98.2 TP30.1 U7.2(VM) U7.11(VM) U7.12(VM) U7.21(VM)
ACCEL/DECEL: D10.2(A)
DIR/IN2: U7.40(DIR)
DRV_ENABLE: D9.2(A)
ENABLE/IN1: U7.41(ENABLE)
EVM_STATUS: D6.2(A)
FAULT: D12.2(A)
GUI_STATUS: D8.2(A)
ID1: R99.2 R105.1
ID2: R100.2 R106.1
ID3: R101.2 R107.1
ID4: R102.2 R108.1
ID5: R103.2 R109.1
INDEXER HOME: D11.2(A)
MODE2/IPROPI4: J16.2 R79.2 U7.29(Reserved)
MODE/MODE1: U7.28(MODE)
nFAULT: R83.1 R112.1 U7.26(~{FAULT})
nHOME/OCPM: R88.1 U7.27(~{HOME})
nSCS/M0/EN4/VREF1/VREF: U7.34(~{SCS}/M0)
nSLEEP: U7.42(~{SLEEP})
PUSH: J27.3
RST/SBWTDIO: J27.1
RSVD/IPROPI1/IPROPI2/IPROPI: J17.2 R80.2 U7.32(Reserved)
RSVD/IPROPI2/IPROPI1/IPROPI: J18.2 J19.2 R81.2 U7.31(Reserved)
RSVD/IPROPI3: J19.1 J20.2 R82.2 U7.30(Reserved)
RSVD/TOFF/EN3: U7.35(Reserved/TOFF)
SCLK/M1/IN4/RSVD: U7.38(SCLK/M1)
SDI/DECAY0/EN1/DECAY: U7.37(SDI/DECAY0)
SDO/DECAY1/EN2/RSVD: U7.36(SDO/DECAY1)
STEP/IN3/RSVD: U7.39(STEP)
VREF/VREF2: U7.33(VREF)
VSEN_AOUT1: C67.1 R89.1 R93.2
VSEN_AOUT2: C68.1 R90.1 R94.2
VSEN_BOUT1: C69.1 R91.1 R95.2
VSEN_BOUT2: C70.1 R92.1 R96.2
VSEN_VM: C71.1 R98.1 R104.2
NetC50_1: C50.1 U7.44(CPH)
NetC50_2: C50.2 U7.43(CPL)
NetC51_2: C51.2 U7.1(VCP)
NetD4_1: D4.1(K) Q1.3(C)
NetD5_1: D5.1(K) R110.2
NetD6_1: D6.1(K) R114.2
NetD7_1: D7.1(K) R112.2
NetD8_1: D8.1(K) R113.2
NetD9_1: D9.1(K) R115.2
NetD10_1: D10.1(K) R111.2
NetD11_1: D11.1(K) R116.2
NetD12_1: D12.1(K) R117.2
NetD13_1: D13.1(C) Q1.1(B) R97.1
NetF1_2: F1.2 J12.2
NetJ16_1: J16.1 R79.1 R84.2
NetJ17_1: J17.1 R80.1 R85.2
NetJ18_1: J18.1 R81.1 R86.2
NetJ20_1: J20.1 R82.1 R87.2
NetJ27_2: J27.2 S1.1
NetQ1_2: Q1.2(E) R118.2

Not connected (* = marked no-connect by the designer): J15 2; J21 2; S1 2*

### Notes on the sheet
- Motor Driver
- 4.5 - 48V DC (DRV8452; DRV8252, DRV8952)
- 4.5 - 60V DC (DRV8462; DRV8262, DRV8962)
- Tie pin 2  of J17 and pin 2 of J18  together for DRV8262 single bridge
- (near J24) DNP J22 and J24, for parallel mode
- (near R79) Select R_IPROPI, connect to disable current regulation
- LEDS
- ID
- BUTTON
- SELECT PUSH
- BUTTON FUNCT
- DEFAULT
- PINS 1-2

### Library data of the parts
C49 C51 = CMP-0007873-2: CAP, CERM, 1 uF, 50 V, +/- 10%, X7R, 0805; Manufacturer: TDK; TaMin_C: -55°C; ESR_ohm: 8.782m; Polarized: N; SizeAreaWB_mm2: 6.75; Value1: 0.008782 ohm; U/M: EA; Value: 1uF; TaMax_C: 125°C; SizeZ_mm: 1.45; SizeX_mm: 2; SizeY_mm: 1.25; Cap_Case: 0805; SizeArea_mm2: 2.5; IRMS_A: 2.2049A; AEC Category: Q200
C50 C55 = CMP-14477-003474-1: Ceramic Capacitor General Use 0.1uF ±20% 100V X5R 0603
C52 C54 C60 C61 C64-C66 = CMP-2006-03016-2: CAP CER 1000PF 100V X7R 0603; Manufacturer: KEMET; Material: Ceramic; Automotive Grade: Grade 1; Temperature Coefficient: 30ppm/°C; Tolerance: 0.1
C53 = CMP-0094051-1: 100uF 100V 20% Aluminum Electrolytic Capacitors Radial, Can - SMD - 5000 Hrs @ 105°C; Manufacturer: United Chemi-Con; Value: 100µF; IRMS_A: 450mA; Life: 5000Hours; SizeZ_mm: 14mm; AEC Grade: Grade 2; Leakage Current: 100uA; Dissipation Factor: 10%; AEC Qualified: Yes
C56 = CMP-06035-000063-1: CAP CER 1UF 100V X7S 0805; Manufacturer: Murata; Tolerance: 10%; Material: Ceramic; Temperature Coefficient: 22%
C57-C59 = CMP-14477-001102-1: Ceramic Capacitor General Use 0.01uF ±20% 100V X7R 0603
C63 = CMP-1035-02591-1: CAP 100nF 50V ±5% 0603 (1608 Metric) Thickness 1mm SMD; Tolerance: Â±5%; Case-Metric: 1608; Case-EIA: 0603
C67-C71 = CMP-0087080-2: CAP CER 100PF 100V X8R 0402; Manufacturer: Kemet; AEC Qualified: No; TempCo: 15%; SizeZ_mm: 0.55mm; Tolerance_%: 5%; AEC Grade: NA; Symbol Name: SYM-C0402C101J1HAC
D4 = CMP-1426-00004-1: SMD mono-color Chip LED, WL-SMCW, Super Red; Manufacturer: Wuerth Elektronik
D5 D6 D8 = CMP-0002894-2: LED, Green, SMD; Manufacturer: Wurth Elektronik; Type: AlInGaP; Value2: 2V; Io_A: 20mA; Value1: W
D7 = CMP-0002893-1: LED, Super Red, SMD; Manufacturer: Wurth Elektronik; Io_A: 20mA; Value1: W; U/M: EA; Vf_V: 1.9V; Type: AlInGaP
D9 = CMP-0002892-3: LED, Yellow, SMD; Manufacturer: Wurth Elektronik; Value1: W; Vf_V: 2V; Type: AlInGaP; Io_A: 20mA
D10 D11 = CMP-0002892-3: LED, Yellow, SMD; Manufacturer: Wurth Elektronik; Type: AlInGaP; Value2: 2V; Io_A: 20mA; Value1: W
D12 = CMP-0002892-3: LED, Yellow, SMD; Manufacturer: Wurth Elektronik; Io_A: 20mA; Value1: W; Vf_V: 2V; Type: AlInGaP
D13 = CMP-14400-000003-1: DIODE ZENER 4.7V 550MW SOD323F; Manufacturer: Nexperia; Forward Current: 250mA; Max Junction Temp: +150°C; Max Reverse Leakage Current: 3uA; Automotive Grade: Grade 0; Zener Impedance: 80Ω; Max Zener Voltage: 4.79V; Reverse Voltage: 2V
F1 = CMP-0081016-1: Fuse, 15 A, 250 VAC, 100 VDC, SMD; Manufacturer: Littelfuse; TaMin_C: -55°C; Irating_A: 15A; SizeAreaWB_mm2: 61.952; Interrupt_AC: 100A; Interrupt_DC: 50A; VAC_V: 250V; TaMax_C: 125°C; Fuse Speed: Fast; SizeZ_mm: 3.12; SizeX_mm: 10.1; SizeArea_mm2: 31.512; VDC_V: 100V; Fuse Technology: Board Mount; Rtyp_Ohm: 4.7m; MeltingTyp: 142
J12 = CMP-0086764-1: Manufacturer: Wurth; Current_A: 57A; Voltage_V: 750V; ContactFinish: Zinc; Row_Count: 1
J13 J14 J23 = CMP-0093233-1: 2 Position Wire to Board Terminal Block Horizontal with Board 0.250" (6.35mm) Through Hole; Manufacturer: Wurth Electronics; Current_A: 32A; Conn Gender: Female; Row_Count: 1; ContactFinish: Zinc; SizeZ_mm: 21.6mm; Max Wire Gauge: 10; Min Wire Gauge: 30; Voltage_V: 450V; AEC Qualified: No; Is Female: yes
J15 J21 J22 J24 = CMP-0075110-1: 1mm Uninsulated Shorting Plug, 10.16mm spacing, TH; Manufacturer: Harwin; CNHeader: False; Green_Lifecycle: Active; Green_REACh: Passed; CompType: Jumper Wire
J16-J20 = CMP-0054566-1: as J5 on sheet MD040_Motor_control_RevE2
J27 = CMP-77940-000002-1: CONN HEADER VERT 3POS 2.54MM; Manufacturer: Metz Connect; Conn Orientation: Straight; Current Rating: 3A; Number Of Contacts: 3; Conn Gender: Male
Q1 = CMP-1048-00779-1: General Purpose Transistor, NPN Silicon, 3-Pin SOT-23, Pb-Free, Tape and Reel; Manufacturer: On Semiconductor; fT Min (MHz): 100; IC Continuous (A): 0.1
R79-R82 = CMP-0026695-1: RES, 3.30 k, 1%, 0.1 W, AEC-Q200 Grade 0, 0402; Manufacturer: Panasonic; Power_W: 100mW; TempCo: 100 ppm/C; Value_Code: 3k30; U/M: EA; Value: 3.30k; Res_ohm: 3.3k; SizeX_mm: 1; SizeY_mm: 0.5; SizeZ_mm: 0.6; Value2: 0.1W; AEC Qualified: Y; VDC_V: 50V; AEC Grade: 0; AEC Category: Q200
R83 R88 = CMP-0025886-3: RES, 10 k, 5%, 0.1 W, 0603; Manufacturer: Yageo America; Power_W: 100mW; TempCo: 100 ppm/C; Value_Code: 10k0; U/M: EA; Value: 10k; EIA_Code: E24; SizeX_mm: 1.6; SizeY_mm: 0.8; SizeZ_mm: 1; Value2: 0.1W; SizeArea_mm2: 1.28; VDC_V: 50V; AEC Category: Q200
R84-R87 = CMP-0081856-1: RES, 0, 0%, 0.2 W, AEC-Q200 Grade 0, 0402; Manufacturer: Vishay-Dale; SizeAreaWB_mm2: 3; SizeArea_mm2: 0.5; AEC Qualified: Y; AEC Category: Q200; Value: 0; SizeZ_mm: 0.6; Power_W: 200mW; VDC_V: 50V; Value2: 0.2W; SizeX_mm: 1
R89-R92 = CMP-0022628-3: RES, 86.6 k, 1%, 0.1 W, 0603; Manufacturer: Vishay-Dale; Value: 86.6k; Value_Code: 86k6; Power_W: 100mW; Value2: 0.1W; VDC_V: 75V; TempCo: 100 ppm/C; EIA_Code: E96; U/M: EA; AEC Category: Q200; SizeY_mm: 0.8; SizeZ_mm: 1; SizeArea_mm2: 1.28; SizeX_mm: 1.6
R93-R96 R104 = CMP-0022458-4: RES, 4.99 k, 1%, 0.1 W, AEC-Q200 Grade 0, 0603; Manufacturer: Vishay-Dale; Value: 4.99k; Value_Code: 4k99; Power_W: 100mW; Value2: 0.1W; VDC_V: 75V; TempCo: 100 ppm/C; EIA_Code: E96; SizeX_mm: 1.6; SizeY_mm: 0.8; SizeZ_mm: 1; SizeArea_mm2: 1.28; AEC Qualified: Y; AEC Category: Q200; AEC Grade: 0
R97 = CMP-0026935-3: RES, 47 k, 5%, 0.063 W, AEC-Q200 Grade 0, 0402; Manufacturer: Vishay-Dale; Power_W: 63mW; TempCo: 200 ppm/C; Value_Code: 47k0; Value: 47k; EIA_Code: E24; SizeX_mm: 1; SizeY_mm: 0.5; SizeZ_mm: 0.6; Value2: 0.063W; AEC Qualified: Y; VDC_V: 50V; AEC Category: Q200; AEC Grade: 0
R98 = CMP-0025663-3: RES, 97.6 k, 0.5%, 0.1 W, 0603; Manufacturer: Yageo America; Value: 97.6k; Value_Code: 97k6; Power_W: 100mW; Value2: 0.1W; VDC_V: 75V; TempCo: 50 ppm/C; EIA_Code: E192; U/M: EA; AEC Category: Q200; SizeY_mm: 0.8; SizeZ_mm: 1; SizeArea_mm2: 1.28; SizeX_mm: 1.6
R99-R103 R105-R109 = CMP-0025886-5: RES, 10 k, 5%, 0.1 W, 0603; Manufacturer: Yageo; Power_W: 100mW; TempCo: 100 ppm/C; Value_Code: 10k0; Value: 10k; EIA_Code: E24; SizeX_mm: 1.6; SizeY_mm: 0.8; SizeZ_mm: 1; Value2: 0.1W; SizeArea_mm2: 1.28; AEC Qualified: N; VDC_V: 75V; AEC Category: Q200; SizeAreaWB_mm2: 4.68
R110 = CMP-0023183-5: RES, 560, 1%, 0.1 W, 0603; Manufacturer: Yageo; Power_W: 100mW; TempCo: 100 ppm/C; Value_Code: 560R; Value: 560; SizeX_mm: 1.6; SizeY_mm: 0.8; SizeZ_mm: 1; Value2: 0.1W; SizeArea_mm2: 1.28; AEC Qualified: N; VDC_V: 75V; AEC Category: Q200; SizeAreaWB_mm2: 4.68
R111-R117 = CMP-0025785-4: RES, 330, 5%, 0.1 W, AEC-Q200 Grade 0, 0603; PartNumber: CRCW0603330RJNEA; Manufacturer: Vishay-Dale; CompType: Resistor; Value: 330; Value_Code: 330R; Power_W: 100mW; Value2: 0.1W; VDC_V: 75V; TempCo: 200 ppm/C; EIA_Code: E24; AEC Category: Q200; AEC Qualified: Y; AEC Grade: 0; SizeX_mm: 1.6; SizeY_mm: 0.8; SizeZ_mm: 1; SizeArea_mm2: 1.28
R118 = CMP-0023129-5: RES, 470, 1%, 0.1 W, 0603; Manufacturer: Yageo; Power_W: 100mW; TempCo: 100 ppm/C; Value_Code: 470R; Value: 470; SizeX_mm: 1.6; SizeY_mm: 0.8; SizeZ_mm: 1; Value2: 0.1W; SizeArea_mm2: 1.28; AEC Qualified: N; VDC_V: 75V; AEC Category: Q200; SizeAreaWB_mm2: 4.68
S1 = CMP-0002134-3: Switch, Tactile, SPST-NO, 0.05A, 12V, SMT; Manufacturer: TE Connectivity; CurrentRating_mA: 50A; PositionCount: 1; SwitchFunction: Off-Mom
SH-J18-SH-J22 = CMP-0003623-1: as SH-J1 on sheet MD040_Motor_control_RevE2
TP28 TP30 = CMP-0055147-1: as TP27 on sheet MD040_Motor_control_RevE2
TP29 = CMP-0055148-1: as TP25 on sheet MD040_Motor_control_RevE2
TP31 TP32 TP34 TP35 = CMP-0055152-1: Test Point, Miniature, SMT; Manufacturer: Keystone; CNHeader: FALSE; Green_Lifecycle: Active; Green_REACh: Passed; CT: TRUE
U7 = CMP-0093481-2: Stepper Motor Driver with Automatic Microstepping, Silent step Decay Mode  and Auto-torque; Manufacturer: Texas Instruments; TJmax_C: +150°C; TaMin_C: -40°C; Standoff Height: 0.05mm; Number Of Outputs: 4; Nominal Supply Current: 3-7mA; AEC Qualified: No; Max Supply Voltage: 48V; AEC Category: Q200; Min Supply Voltage: 4.5V; TaMax_C: +125°C; Switching Frequency: 500kHz; CompType: IC; SizeZ_mm: 1.2mm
